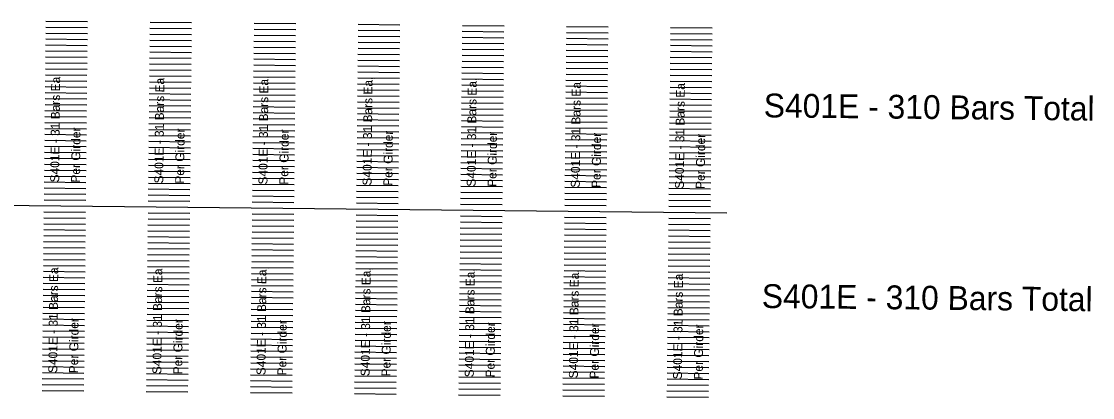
# Model space of a CAD drawing. Extents: x 632547 to 633311, y 380830 to 386139.
# Drawn here: x 633155.8 to 633245.8, y 381143.9 to 381175.5 of the extents above; entities that cross this region are included whole.
import ezdxf

# ---------------------------------------------------------------- set-up
doc = ezdxf.new("R2010")
doc.units = 0
for name, color, linetype in [('B_Border', 7, 'Continuous'), ('R_Border_Scale', 7, 'Continuous'), ('R_Wall', 7, 'Continuous')]:
    doc.layers.add(name, color=color, linetype=linetype)

msp = doc.modelspace()

# ---------------------------------------------------------------- linework, layer by layer
at = {"layer": 'B_Border'}
msp.add_line((633215.055, 381159.402), (633098.001, 381160.586), dxfattribs=at)
at = {"layer": 'R_Border_Scale'}
for p, q in [((633161.334, 381174.946), (633157.835, 381174.982)), ((633161.339, 381175.446), (633157.84, 381175.481)), ((633170.084, 381174.858), (633166.584, 381174.893)), ((633170.089, 381175.358), (633166.589, 381175.393)), ((633178.833, 381174.769), (633175.334, 381174.804)), ((633178.839, 381175.269), (633175.339, 381175.304)), ((633187.583, 381174.681), (633184.083, 381174.716)), ((633187.588, 381175.181), (633184.088, 381175.216)), ((633196.338, 381175.092), (633192.838, 381175.127)), ((633205.087, 381175.003), (633201.587, 381175.039)), ((633213.837, 381174.915), (633210.337, 381174.95)), ((633161.324, 381173.946), (633157.824, 381173.982)), ((633161.329, 381174.446), (633157.829, 381174.482)), ((633170.074, 381173.858), (633166.574, 381173.893)), ((633170.079, 381174.358), (633166.579, 381174.393)), ((633178.823, 381173.769), (633175.324, 381173.805)), ((633178.828, 381174.269), (633175.329, 381174.304)), ((633187.578, 381174.181), (633184.078, 381174.216)), ((633196.328, 381174.092), (633192.828, 381174.127)), ((633196.333, 381174.592), (633192.833, 381174.627)), ((633205.077, 381174.004), (633201.577, 381174.039)), ((633205.082, 381174.503), (633201.582, 381174.539)), ((633213.827, 381173.915), (633210.327, 381173.95)), ((633213.832, 381174.415), (633210.332, 381174.45)), ((633161.314, 381172.946), (633157.814, 381172.982)), ((633161.319, 381173.446), (633157.819, 381173.482)), ((633170.064, 381172.858), (633166.564, 381172.893)), ((633170.069, 381173.358), (633166.569, 381173.393)), ((633178.818, 381173.269), (633175.318, 381173.305)), ((633187.568, 381173.181), (633184.068, 381173.216)), ((633187.573, 381173.681), (633184.073, 381173.716)), ((633196.317, 381173.092), (633192.818, 381173.128)), ((633196.322, 381173.592), (633192.823, 381173.627)), ((633205.067, 381173.004), (633201.567, 381173.039)), ((633205.072, 381173.504), (633201.572, 381173.539)), ((633213.817, 381172.915), (633210.317, 381172.95)), ((633213.822, 381173.415), (633210.322, 381173.45)), ((633161.304, 381171.946), (633157.804, 381171.982)), ((633161.309, 381172.446), (633157.809, 381172.482)), ((633170.059, 381172.358), (633166.559, 381172.393)), ((633178.808, 381172.269), (633175.308, 381172.305)), ((633178.813, 381172.769), (633175.313, 381172.805)), ((633187.558, 381172.181), (633184.058, 381172.216)), ((633187.563, 381172.681), (633184.063, 381172.716)), ((633196.307, 381172.092), (633192.807, 381172.128)), ((633196.312, 381172.592), (633192.813, 381172.628)), ((633205.057, 381172.004), (633201.557, 381172.039)), ((633205.062, 381172.504), (633201.562, 381172.539)), ((633213.811, 381172.415), (633210.312, 381172.45)), ((633161.299, 381171.446), (633157.799, 381171.482)), ((633170.049, 381171.358), (633166.549, 381171.393)), ((633170.054, 381171.858), (633166.554, 381171.893)), ((633178.798, 381171.269), (633175.298, 381171.305)), ((633178.803, 381171.769), (633175.303, 381171.805)), ((633187.548, 381171.181), (633184.048, 381171.216)), ((633187.553, 381171.681), (633184.053, 381171.716)), ((633196.297, 381171.092), (633192.797, 381171.128)), ((633196.302, 381171.592), (633192.802, 381171.628)), ((633205.052, 381171.504), (633201.552, 381171.539)), ((633213.801, 381171.415), (633210.302, 381171.451)), ((633213.806, 381171.915), (633210.307, 381171.951)), ((633161.289, 381170.446), (633157.789, 381170.482)), ((633161.294, 381170.946), (633157.794, 381170.982)), ((633170.038, 381170.358), (633166.539, 381170.393)), ((633170.043, 381170.858), (633166.544, 381170.893)), ((633178.788, 381170.269), (633175.288, 381170.305)), ((633178.793, 381170.769), (633175.293, 381170.805)), ((633187.538, 381170.181), (633184.038, 381170.216)), ((633187.543, 381170.681), (633184.043, 381170.716)), ((633196.292, 381170.592), (633192.792, 381170.628)), ((633205.042, 381170.504), (633201.542, 381170.539)), ((633205.047, 381171.004), (633201.547, 381171.039)), ((633213.791, 381170.415), (633210.291, 381170.451)), ((633213.796, 381170.915), (633210.296, 381170.951)), ((633161.279, 381169.446), (633157.779, 381169.482)), ((633161.284, 381169.946), (633157.784, 381169.982)), ((633170.028, 381169.358), (633166.528, 381169.393)), ((633170.033, 381169.858), (633166.534, 381169.893)), ((633178.778, 381169.269), (633175.278, 381169.305)), ((633178.783, 381169.769), (633175.283, 381169.805)), ((633187.532, 381169.681), (633184.033, 381169.716)), ((633196.282, 381169.592), (633192.782, 381169.628)), ((633196.287, 381170.092), (633192.787, 381170.128)), ((633205.032, 381169.504), (633201.532, 381169.539)), ((633205.037, 381170.004), (633201.537, 381170.039)), ((633213.781, 381169.415), (633210.281, 381169.451)), ((633213.786, 381169.915), (633210.286, 381169.951)), ((633161.269, 381168.446), (633157.769, 381168.482)), ((633161.274, 381168.946), (633157.774, 381168.982)), ((633170.018, 381168.358), (633166.518, 381168.393)), ((633170.023, 381168.858), (633166.523, 381168.893)), ((633178.773, 381168.769), (633175.273, 381168.805)), ((633187.522, 381168.681), (633184.023, 381168.716)), ((633187.527, 381169.181), (633184.028, 381169.216)), ((633196.272, 381168.592), (633192.772, 381168.628)), ((633196.277, 381169.092), (633192.777, 381169.128)), ((633205.021, 381168.504), (633201.522, 381168.539)), ((633205.026, 381169.004), (633201.527, 381169.039)), ((633213.771, 381168.415), (633210.271, 381168.451)), ((633213.776, 381168.915), (633210.276, 381168.951)), ((633161.258, 381167.446), (633157.759, 381167.482)), ((633161.264, 381167.946), (633157.764, 381167.982)), ((633170.013, 381167.858), (633166.513, 381167.893)), ((633178.763, 381167.769), (633175.263, 381167.805)), ((633178.768, 381168.269), (633175.268, 381168.305)), ((633187.512, 381167.681), (633184.012, 381167.716)), ((633187.517, 381168.181), (633184.017, 381168.216)), ((633196.262, 381167.592), (633192.762, 381167.628)), ((633196.267, 381168.092), (633192.767, 381168.128)), ((633205.011, 381167.504), (633201.511, 381167.539)), ((633205.016, 381168.004), (633201.517, 381168.039)), ((633213.766, 381167.915), (633210.266, 381167.951)), ((633161.253, 381166.947), (633157.754, 381166.982)), ((633170.003, 381166.858), (633166.503, 381166.893)), ((633170.008, 381167.358), (633166.508, 381167.393)), ((633178.753, 381166.769), (633175.253, 381166.805)), ((633178.758, 381167.269), (633175.258, 381167.305)), ((633187.502, 381166.681), (633184.002, 381166.716)), ((633187.507, 381167.181), (633184.007, 381167.216)), ((633196.252, 381166.592), (633192.752, 381166.628)), ((633196.257, 381167.092), (633192.757, 381167.128)), ((633205.006, 381167.004), (633201.506, 381167.039)), ((633213.756, 381166.915), (633210.256, 381166.951)), ((633213.761, 381167.415), (633210.261, 381167.451)), ((633161.243, 381165.947), (633157.744, 381165.982)), ((633161.248, 381166.447), (633157.749, 381166.482)), ((633169.993, 381165.858), (633166.493, 381165.893)), ((633169.998, 381166.358), (633166.498, 381166.393)), ((633178.742, 381165.77), (633175.243, 381165.805)), ((633178.747, 381166.269), (633175.248, 381166.305)), ((633187.492, 381165.681), (633183.992, 381165.716)), ((633187.497, 381166.181), (633183.997, 381166.216)), ((633196.247, 381166.092), (633192.747, 381166.128)), ((633204.996, 381166.004), (633201.496, 381166.039)), ((633205.001, 381166.504), (633201.501, 381166.539)), ((633213.746, 381165.915), (633210.246, 381165.951)), ((633213.751, 381166.415), (633210.251, 381166.451)), ((633161.233, 381164.947), (633157.733, 381164.982)), ((633161.238, 381165.447), (633157.738, 381165.482)), ((633169.983, 381164.858), (633166.483, 381164.893)), ((633169.988, 381165.358), (633166.488, 381165.393)), ((633178.732, 381164.77), (633175.232, 381164.805)), ((633178.737, 381165.27), (633175.238, 381165.305)), ((633187.487, 381165.181), (633183.987, 381165.216)), ((633196.236, 381165.093), (633192.737, 381165.128)), ((633196.242, 381165.592), (633192.742, 381165.628)), ((633204.986, 381165.004), (633201.486, 381165.039)), ((633204.991, 381165.504), (633201.491, 381165.539)), ((633213.736, 381164.915), (633210.236, 381164.951)), ((633213.741, 381165.415), (633210.241, 381165.451)), ((633161.223, 381163.947), (633157.723, 381163.982)), ((633161.228, 381164.447), (633157.728, 381164.482)), ((633169.973, 381163.858), (633166.473, 381163.894)), ((633169.978, 381164.358), (633166.478, 381164.394)), ((633178.727, 381164.27), (633175.227, 381164.305)), ((633187.477, 381164.181), (633183.977, 381164.216)), ((633187.482, 381164.681), (633183.982, 381164.716)), ((633196.226, 381164.093), (633192.727, 381164.128)), ((633196.231, 381164.593), (633192.732, 381164.628)), ((633204.976, 381164.004), (633201.476, 381164.039)), ((633204.981, 381164.504), (633201.481, 381164.539)), ((633213.725, 381163.916), (633210.226, 381163.951)), ((633213.731, 381164.415), (633210.231, 381164.451)), ((633161.213, 381162.947), (633157.713, 381162.982)), ((633161.218, 381163.447), (633157.718, 381163.482)), ((633169.968, 381163.358), (633166.468, 381163.394)), ((633178.717, 381163.27), (633175.217, 381163.305)), ((633178.722, 381163.77), (633175.222, 381163.805)), ((633187.467, 381163.181), (633183.967, 381163.217)), ((633187.472, 381163.681), (633183.972, 381163.717)), ((633196.216, 381163.093), (633192.716, 381163.128)), ((633196.221, 381163.593), (633192.721, 381163.628)), ((633204.966, 381163.004), (633201.466, 381163.039)), ((633204.971, 381163.504), (633201.471, 381163.539)), ((633213.72, 381163.416), (633210.221, 381163.451)), ((633161.208, 381162.447), (633157.708, 381162.482)), ((633169.957, 381162.358), (633166.458, 381162.394)), ((633169.963, 381162.858), (633166.463, 381162.894)), ((633178.707, 381162.27), (633175.207, 381162.305)), ((633178.712, 381162.77), (633175.212, 381162.805)), ((633187.457, 381162.181), (633183.957, 381162.217)), ((633187.462, 381162.681), (633183.962, 381162.717)), ((633196.206, 381162.093), (633192.706, 381162.128)), ((633196.211, 381162.593), (633192.711, 381162.628)), ((633204.961, 381162.504), (633201.461, 381162.54)), ((633213.71, 381162.416), (633210.21, 381162.451)), ((633213.715, 381162.916), (633210.216, 381162.951)), ((633161.198, 381161.447), (633157.698, 381161.482)), ((633161.203, 381161.947), (633157.703, 381161.982)), ((633169.947, 381161.358), (633166.448, 381161.394)), ((633169.952, 381161.858), (633166.453, 381161.894)), ((633178.697, 381161.27), (633175.197, 381161.305)), ((633178.702, 381161.77), (633175.202, 381161.805)), ((633187.446, 381161.181), (633183.947, 381161.217)), ((633187.452, 381161.681), (633183.952, 381161.717)), ((633196.201, 381161.593), (633192.701, 381161.628)), ((633204.951, 381161.504), (633201.451, 381161.54)), ((633204.956, 381162.004), (633201.456, 381162.04)), ((633213.7, 381161.416), (633210.2, 381161.451)), ((633213.705, 381161.916), (633210.205, 381161.951)), ((633161.188, 381160.447), (633157.688, 381160.482)), ((633161.193, 381160.947), (633157.693, 381160.982)), ((633169.937, 381160.358), (633166.437, 381160.394)), ((633169.942, 381160.858), (633166.442, 381160.894)), ((633178.687, 381160.27), (633175.187, 381160.305)), ((633178.692, 381160.77), (633175.192, 381160.805)), ((633187.441, 381160.681), (633183.942, 381160.717)), ((633196.191, 381160.593), (633192.691, 381160.628)), ((633196.196, 381161.093), (633192.696, 381161.128)), ((633204.941, 381160.504), (633201.441, 381160.54)), ((633204.946, 381161.004), (633201.446, 381161.04)), ((633213.69, 381160.416), (633210.19, 381160.451)), ((633213.695, 381160.916), (633210.195, 381160.951)), ((633161.178, 381159.447), (633157.678, 381159.482)), ((633169.927, 381159.358), (633166.427, 381159.394)), ((633187.436, 381160.181), (633183.937, 381160.217)), ((633196.186, 381160.093), (633192.686, 381160.128)), ((633204.935, 381160.004), (633201.436, 381160.04)), ((633213.685, 381159.916), (633210.185, 381159.951)), ((633161.167, 381158.447), (633157.668, 381158.482)), ((633161.173, 381158.947), (633157.673, 381158.982)), ((633169.922, 381158.858), (633166.422, 381158.894)), ((633178.672, 381158.77), (633175.172, 381158.805)), ((633178.677, 381159.27), (633175.177, 381159.305)), ((633187.421, 381158.681), (633183.921, 381158.717)), ((633187.426, 381159.181), (633183.926, 381159.217)), ((633196.171, 381158.593), (633192.671, 381158.628)), ((633196.176, 381159.093), (633192.676, 381159.128)), ((633204.92, 381158.504), (633201.42, 381158.54)), ((633204.925, 381159.004), (633201.426, 381159.04)), ((633213.675, 381158.916), (633210.175, 381158.951)), ((633161.162, 381157.947), (633157.663, 381157.982)), ((633169.912, 381157.858), (633166.412, 381157.894)), ((633169.917, 381158.358), (633166.417, 381158.394)), ((633178.661, 381157.77), (633175.162, 381157.805)), ((633178.667, 381158.27), (633175.167, 381158.305)), ((633187.411, 381157.681), (633183.911, 381157.717)), ((633187.416, 381158.181), (633183.916, 381158.217)), ((633196.161, 381157.593), (633192.661, 381157.628)), ((633196.166, 381158.093), (633192.666, 381158.128)), ((633204.915, 381158.004), (633201.415, 381158.04)), ((633213.665, 381157.916), (633210.165, 381157.951)), ((633213.67, 381158.416), (633210.17, 381158.451)), ((633161.152, 381156.947), (633157.652, 381156.982)), ((633161.157, 381157.447), (633157.658, 381157.482)), ((633169.902, 381156.858), (633166.402, 381156.894)), ((633169.907, 381157.358), (633166.407, 381157.394)), ((633178.651, 381156.77), (633175.152, 381156.805)), ((633178.656, 381157.27), (633175.157, 381157.305)), ((633187.401, 381156.681), (633183.901, 381156.717)), ((633187.406, 381157.181), (633183.906, 381157.217)), ((633196.156, 381157.093), (633192.656, 381157.128)), ((633204.905, 381157.004), (633201.405, 381157.04)), ((633204.91, 381157.504), (633201.41, 381157.54)), ((633213.655, 381156.916), (633210.155, 381156.951)), ((633213.66, 381157.416), (633210.16, 381157.451)), ((633161.142, 381155.947), (633157.642, 381155.982)), ((633161.147, 381156.447), (633157.647, 381156.482)), ((633169.892, 381155.859), (633166.392, 381155.894)), ((633169.897, 381156.359), (633166.397, 381156.394)), ((633178.641, 381155.77), (633175.141, 381155.805)), ((633178.646, 381156.27), (633175.146, 381156.305)), ((633187.396, 381156.181), (633183.896, 381156.217)), ((633196.145, 381156.093), (633192.646, 381156.128)), ((633196.15, 381156.593), (633192.651, 381156.628)), ((633204.895, 381156.004), (633201.395, 381156.04)), ((633204.9, 381156.504), (633201.4, 381156.54)), ((633213.645, 381155.916), (633210.145, 381155.951)), ((633213.65, 381156.416), (633210.15, 381156.451)), ((633161.132, 381154.947), (633157.632, 381154.983)), ((633161.137, 381155.447), (633157.637, 381155.483)), ((633169.882, 381154.859), (633166.382, 381154.894)), ((633169.887, 381155.359), (633166.387, 381155.394)), ((633178.636, 381155.27), (633175.136, 381155.305)), ((633187.386, 381155.182), (633183.886, 381155.217)), ((633187.391, 381155.682), (633183.891, 381155.717)), ((633196.135, 381155.093), (633192.635, 381155.128)), ((633196.14, 381155.593), (633192.641, 381155.628)), ((633204.885, 381155.004), (633201.385, 381155.04)), ((633204.89, 381155.504), (633201.39, 381155.54)), ((633213.634, 381154.916), (633210.135, 381154.951)), ((633213.639, 381155.416), (633210.14, 381155.451)), ((633161.122, 381153.947), (633157.622, 381153.983)), ((633161.127, 381154.447), (633157.627, 381154.483)), ((633169.877, 381154.359), (633166.377, 381154.394)), ((633178.626, 381154.27), (633175.126, 381154.306)), ((633178.631, 381154.77), (633175.131, 381154.805)), ((633187.376, 381154.182), (633183.876, 381154.217)), ((633187.381, 381154.682), (633183.881, 381154.717)), ((633196.125, 381154.093), (633192.625, 381154.128)), ((633196.13, 381154.593), (633192.63, 381154.628)), ((633204.875, 381154.005), (633201.375, 381154.04)), ((633204.88, 381154.505), (633201.38, 381154.54)), ((633213.629, 381154.416), (633210.13, 381154.451)), ((633161.117, 381153.447), (633157.617, 381153.483)), ((633169.866, 381153.359), (633166.367, 381153.394)), ((633169.871, 381153.859), (633166.372, 381153.894)), ((633178.616, 381153.27), (633175.116, 381153.306)), ((633178.621, 381153.77), (633175.121, 381153.806)), ((633187.366, 381153.182), (633183.866, 381153.217)), ((633187.371, 381153.682), (633183.871, 381153.717)), ((633196.115, 381153.093), (633192.615, 381153.129)), ((633196.12, 381153.593), (633192.62, 381153.628)), ((633204.87, 381153.505), (633201.37, 381153.54)), ((633213.619, 381153.416), (633210.119, 381153.451)), ((633213.624, 381153.916), (633210.124, 381153.951)), ((633161.107, 381152.447), (633157.607, 381152.483)), ((633161.112, 381152.947), (633157.612, 381152.983)), ((633169.856, 381152.359), (633166.356, 381152.394)), ((633169.861, 381152.859), (633166.362, 381152.894)), ((633178.606, 381152.27), (633175.106, 381152.306)), ((633178.611, 381152.77), (633175.111, 381152.806)), ((633187.355, 381152.182), (633183.856, 381152.217)), ((633187.36, 381152.682), (633183.861, 381152.717)), ((633196.11, 381152.593), (633192.61, 381152.629)), ((633204.86, 381152.505), (633201.36, 381152.54)), ((633204.865, 381153.005), (633201.365, 381153.04)), ((633213.609, 381152.416), (633210.109, 381152.452)), ((633213.614, 381152.916), (633210.114, 381152.951)), ((633161.097, 381151.447), (633157.597, 381151.483)), ((633161.102, 381151.947), (633157.602, 381151.983)), ((633169.846, 381151.359), (633166.346, 381151.394)), ((633169.851, 381151.859), (633166.351, 381151.894)), ((633178.596, 381151.27), (633175.096, 381151.306)), ((633178.601, 381151.77), (633175.101, 381151.806)), ((633187.35, 381151.682), (633183.851, 381151.717)), ((633196.1, 381151.593), (633192.6, 381151.629)), ((633196.105, 381152.093), (633192.605, 381152.129)), ((633204.849, 381151.505), (633201.35, 381151.54)), ((633204.855, 381152.005), (633201.355, 381152.04)), ((633213.599, 381151.416), (633210.099, 381151.452)), ((633213.604, 381151.916), (633210.104, 381151.952)), ((633161.087, 381150.447), (633157.587, 381150.483)), ((633161.092, 381150.947), (633157.592, 381150.983)), ((633169.836, 381150.359), (633166.336, 381150.394)), ((633169.841, 381150.859), (633166.341, 381150.894)), ((633178.591, 381150.77), (633175.091, 381150.806)), ((633187.34, 381150.682), (633183.84, 381150.717)), ((633187.345, 381151.182), (633183.845, 381151.217)), ((633196.09, 381150.593), (633192.59, 381150.629)), ((633196.095, 381151.093), (633192.595, 381151.129)), ((633204.839, 381150.505), (633201.34, 381150.54)), ((633204.844, 381151.005), (633201.345, 381151.04)), ((633213.589, 381150.416), (633210.089, 381150.452)), ((633213.594, 381150.916), (633210.094, 381150.952)), ((633161.076, 381149.447), (633157.577, 381149.483)), ((633161.081, 381149.947), (633157.582, 381149.983)), ((633169.831, 381149.859), (633166.331, 381149.894)), ((633178.581, 381149.77), (633175.081, 381149.806)), ((633178.586, 381150.27), (633175.086, 381150.306)), ((633187.33, 381149.682), (633183.83, 381149.717)), ((633187.335, 381150.182), (633183.835, 381150.217)), ((633196.08, 381149.593), (633192.58, 381149.629)), ((633196.085, 381150.093), (633192.585, 381150.129)), ((633204.829, 381149.505), (633201.329, 381149.54)), ((633204.834, 381150.005), (633201.334, 381150.04)), ((633213.584, 381149.916), (633210.084, 381149.952)), ((633161.071, 381148.947), (633157.572, 381148.983)), ((633169.821, 381148.859), (633166.321, 381148.894)), ((633169.826, 381149.359), (633166.326, 381149.394)), ((633178.57, 381148.77), (633175.071, 381148.806)), ((633178.576, 381149.27), (633175.076, 381149.306)), ((633187.32, 381148.682), (633183.82, 381148.717)), ((633187.325, 381149.182), (633183.825, 381149.217)), ((633196.07, 381148.593), (633192.57, 381148.629)), ((633196.075, 381149.093), (633192.575, 381149.129)), ((633204.824, 381149.005), (633201.324, 381149.04)), ((633213.574, 381148.916), (633210.074, 381148.952)), ((633213.579, 381149.416), (633210.079, 381149.452)), ((633161.061, 381147.947), (633157.561, 381147.983)), ((633161.066, 381148.447), (633157.566, 381148.483)), ((633169.811, 381147.859), (633166.311, 381147.894)), ((633169.816, 381148.359), (633166.316, 381148.394)), ((633178.56, 381147.77), (633175.061, 381147.806)), ((633178.565, 381148.27), (633175.066, 381148.306)), ((633187.31, 381147.682), (633183.81, 381147.717)), ((633187.315, 381148.182), (633183.815, 381148.217)), ((633196.064, 381148.093), (633192.565, 381148.129)), ((633204.814, 381148.005), (633201.314, 381148.04)), ((633204.819, 381148.505), (633201.319, 381148.54)), ((633213.564, 381147.916), (633210.064, 381147.952)), ((633213.569, 381148.416), (633210.069, 381148.452)), ((633161.051, 381146.948), (633157.551, 381146.983)), ((633161.056, 381147.448), (633157.556, 381147.483)), ((633169.801, 381146.859), (633166.301, 381146.894)), ((633169.806, 381147.359), (633166.306, 381147.394)), ((633178.55, 381146.77), (633175.05, 381146.806)), ((633178.555, 381147.27), (633175.055, 381147.306)), ((633187.305, 381147.182), (633183.805, 381147.217)), ((633196.054, 381147.093), (633192.555, 381147.129)), ((633196.059, 381147.593), (633192.56, 381147.629)), ((633204.804, 381147.005), (633201.304, 381147.04)), ((633204.809, 381147.505), (633201.309, 381147.54)), ((633213.553, 381146.916), (633210.054, 381146.952)), ((633213.559, 381147.416), (633210.059, 381147.452)), ((633161.041, 381145.948), (633157.541, 381145.983)), ((633161.046, 381146.448), (633157.546, 381146.483)), ((633169.791, 381145.859), (633166.291, 381145.894)), ((633169.796, 381146.359), (633166.296, 381146.394)), ((633178.545, 381146.271), (633175.045, 381146.306)), ((633187.295, 381146.182), (633183.795, 381146.217)), ((633187.3, 381146.682), (633183.8, 381146.717)), ((633196.044, 381146.093), (633192.544, 381146.129)), ((633196.049, 381146.593), (633192.549, 381146.629)), ((633204.794, 381146.005), (633201.294, 381146.04)), ((633204.799, 381146.505), (633201.299, 381146.54)), ((633213.543, 381145.916), (633210.044, 381145.952)), ((633213.548, 381146.416), (633210.049, 381146.452)), ((633161.031, 381144.948), (633157.531, 381144.983)), ((633161.036, 381145.448), (633157.536, 381145.483)), ((633169.785, 381145.359), (633166.286, 381145.394)), ((633178.535, 381145.271), (633175.035, 381145.306)), ((633178.54, 381145.771), (633175.04, 381145.806)), ((633187.285, 381145.182), (633183.785, 381145.217)), ((633187.29, 381145.682), (633183.79, 381145.717)), ((633196.034, 381145.094), (633192.534, 381145.129)), ((633196.039, 381145.594), (633192.539, 381145.629)), ((633204.784, 381145.005), (633201.284, 381145.04)), ((633204.789, 381145.505), (633201.289, 381145.54)), ((633213.538, 381145.416), (633210.038, 381145.452)), ((633161.026, 381144.448), (633157.526, 381144.483)), ((633169.775, 381144.359), (633166.276, 381144.395)), ((633169.78, 381144.859), (633166.281, 381144.895)), ((633178.525, 381144.271), (633175.025, 381144.306)), ((633178.53, 381144.771), (633175.03, 381144.806)), ((633187.274, 381144.182), (633183.775, 381144.218)), ((633187.28, 381144.682), (633183.78, 381144.717)), ((633196.024, 381144.094), (633192.524, 381144.129)), ((633196.029, 381144.594), (633192.529, 381144.629)), ((633204.779, 381144.505), (633201.279, 381144.54)), ((633213.528, 381144.417), (633210.028, 381144.452)), ((633213.533, 381144.916), (633210.033, 381144.952)), ((633204.774, 381144.005), (633201.274, 381144.04)), ((633213.523, 381143.917), (633210.023, 381143.952))]:
    msp.add_line(p, q, dxfattribs=at)

# ---------------------------------------------------------------- texts
at = {"layer": 'R_Wall'}
for s, height, rotation, p in [('S401E - 31 Bars Ea,', 0.75, 89.43036, (633158.953, 381161.969)), ('S401E - 31 Bars Ea,', 0.75, 89.43036, (633167.703, 381161.881)), ('S401E - 31 Bars Ea,', 0.75, 89.43036, (633176.452, 381161.792)), ('S401E - 31 Bars Ea,', 0.75, 89.43036, (633185.202, 381161.704)), ('S401E - 31 Bars Ea,', 0.75, 89.43036, (633193.951, 381161.615)), ('S401E - 31 Bars Ea,', 0.75, 89.43036, (633202.701, 381161.527)), ('S401E - 31 Bars Ea,', 0.75, 89.43036, (633211.45, 381161.438)), ('S401E - 310 Bars Total', 2, 359.43036, (633218.155, 381167.435)), ('Per Girder', 0.75, 89.43036, (633160.703, 381161.952)), ('Per Girder', 0.75, 89.43036, (633169.452, 381161.864)), ('Per Girder', 0.75, 89.43036, (633178.202, 381161.775)), ('Per Girder', 0.75, 89.43036, (633186.952, 381161.686)), ('Per Girder', 0.75, 89.43036, (633195.701, 381161.598)), ('Per Girder', 0.75, 89.43036, (633204.451, 381161.509)), ('Per Girder', 0.75, 89.43036, (633213.2, 381161.421)), ('S401E - 31 Bars Ea,', 0.75, 89.43036, (633158.791, 381145.97)), ('S401E - 31 Bars Ea,', 0.75, 89.43036, (633167.541, 381145.882)), ('S401E - 31 Bars Ea,', 0.75, 89.43036, (633176.29, 381145.793)), ('S401E - 31 Bars Ea,', 0.75, 89.43036, (633185.04, 381145.705)), ('S401E - 31 Bars Ea,', 0.75, 89.43036, (633193.789, 381145.616)), ('S401E - 31 Bars Ea,', 0.75, 89.43036, (633202.539, 381145.528)), ('S401E - 31 Bars Ea,', 0.75, 89.43036, (633211.288, 381145.439)), ('S401E - 310 Bars Total', 2, 359.43036, (633217.993, 381151.436)), ('Per Girder', 0.75, 89.43036, (633160.541, 381145.953)), ('Per Girder', 0.75, 89.43036, (633169.291, 381145.864)), ('Per Girder', 0.75, 89.43036, (633178.04, 381145.776)), ('Per Girder', 0.75, 89.43036, (633186.79, 381145.687)), ('Per Girder', 0.75, 89.43036, (633195.539, 381145.599)), ('Per Girder', 0.75, 89.43036, (633204.289, 381145.51)), ('Per Girder', 0.75, 89.43036, (633213.038, 381145.422))]:
    msp.add_text(s, height=height, rotation=rotation, dxfattribs=at).set_placement(p)

doc.saveas('drawing.dxf')
